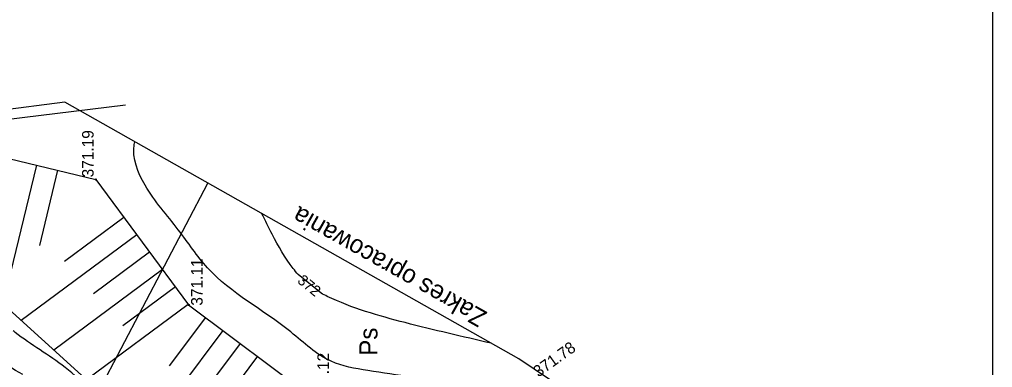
# Model space of a CAD drawing. Extents: x 4635329 to 4651863, y 5356628 to 5367582.
# Drawn here: x 4651263.7 to 4651331.2, y 5356725 to 5356749.2 of the extents above; entities that cross this region are included whole.
import ezdxf

# ---------------------------------------------------------------- set-up
doc = ezdxf.new("R2010")
doc.units = 0
for name, color, linetype in [('Level 1', 7, 'Continuous'), ('Level 12', 7, 'Continuous'), ('Level 13', 7, 'Continuous'), ('Level 39', 7, 'Continuous'), ('Level 4', 7, 'Continuous'), ('Level 44', 7, 'Continuous'), ('Level 45', 7, 'Continuous'), ('Level 46', 7, 'Continuous'), ('Level 47', 7, 'Continuous'), ('Level 48', 7, 'Continuous'), ('Level 6', 7, 'Continuous')]:
    doc.layers.add(name, color=color, linetype=linetype)

msp = doc.modelspace()

# ---------------------------------------------------------------- linework, layer by layer
at = {"layer": 'Level 1'}
for p, q in [((4651266.84, 5356743.443), (4651230.35, 5356738.707)), ((4651298.345, 5356725.644), (4651266.84, 5356743.443)), ((4651328.793, 5356705.271), (4651298.345, 5356725.644))]:
    msp.add_line(p, q, dxfattribs=at)
at = {"layer": 'Level 13'}
msp.add_lwpolyline([(4651092.18, 5356627.729), (4651092.18, 5356813.355), (4651331.195, 5356813.355), (4651331.195, 5356627.729)], close=True, dxfattribs=at)
at = {"layer": 'Level 39'}
msp.add_lwpolyline([(4651250.035, 5356740.377), (4651256.705, 5356741.507), (4651271.061, 5356743.246)], dxfattribs=at)
at = {"layer": 'Level 4'}
msp.add_line((4651265.88, 5356717.076), (4651276.761, 5356737.838), dxfattribs=at)
at = {"layer": 'Level 44'}
for centre in [(4651268.995, 5356738.077), (4651275.435, 5356729.397)]:
    msp.add_circle(centre, 0.04, dxfattribs=at)
at = {"layer": 'Level 46'}
msp.add_line((4651284.619, 5356730.193), (4651283.033, 5356731.486), dxfattribs=at)
for points in [[(4651267.161, 5356715.987), (4651264.708, 5356717.442), (4651260.614, 5356719.868), (4651257.43, 5356722.141), (4651254.792, 5356725.021), (4651252.517, 5356728.872), (4651246.741, 5356739.5), (4651245.898, 5356740.725)], [(4651298.334, 5356723.071), (4651293.949, 5356723.874), (4651287.864, 5356724.843), (4651285.317, 5356725.479), (4651282.527, 5356727.511), (4651276.752, 5356731.958), (4651274.72, 5356734.595), (4651272.415, 5356737.688), (4651271.657, 5356740.507), (4651271.694, 5356740.701)], [(4651283.033, 5356731.486), (4651282.686, 5356731.921), (4651281.229, 5356734.288), (4651280.522, 5356735.713)], [(4651263.931, 5356724.554), (4651261.972, 5356725.806), (4651257.58, 5356731.092)], [(4651296.426, 5356726.728), (4651290.455, 5356728.159), (4651285.053, 5356729.979), (4651284.619, 5356730.193)], [(4651268.687, 5356723.452), (4651266.865, 5356725.056), (4651263.408, 5356727.482), (4651263.267, 5356727.595)], [(4651276.186, 5356713.946), (4651274.753, 5356715.814), (4651267.627, 5356718.36), (4651265.018, 5356720.21), (4651263.442, 5356721.998), (4651259.59, 5356724.848), (4651257.237, 5356726.91)]]:
    msp.add_spline(points, degree=3, dxfattribs=at)
at = {"layer": 'Level 48'}
for p, q in [((4651264.883, 5356739.071), (4651262.556, 5356729.448)), ((4651266.341, 5356738.719), (4651265.081, 5356733.511)), ((4651270.943, 5356735.451), (4651266.816, 5356732.39)), ((4651271.837, 5356734.247), (4651263.823, 5356728.301)), ((4651272.731, 5356733.042), (4651268.844, 5356730.158)), ((4651273.624, 5356731.837), (4651266.091, 5356726.248)), ((4651274.518, 5356730.633), (4651270.872, 5356727.927)), ((4651275.412, 5356729.428), (4651268.359, 5356724.195)), ((4651276.605, 5356728.522), (4651274.097, 5356725.17)), ((4651277.806, 5356727.623), (4651272.839, 5356720.985)), ((4651279.007, 5356726.724), (4651276.548, 5356723.438)), ((4651280.208, 5356725.826), (4651275.338, 5356719.317))]:
    msp.add_line(p, q, dxfattribs=at)
for points in [[(4651283.295, 5356714.007), (4651269.285, 5356723.357), (4651257.365, 5356734.147), (4651256.135, 5356741.187)], [(4651256.135, 5356741.187), (4651268.995, 5356738.077), (4651275.435, 5356729.397), (4651284.135, 5356722.887), (4651292.525, 5356718.537)]]:
    msp.add_lwpolyline(points, dxfattribs=at)

# ---------------------------------------------------------------- texts
at = {"layer": 'Level 12'}
msp.add_text('Ps', height=1.25, rotation=90, dxfattribs=at).set_placement((4651288.531, 5356725.864))
at = {"layer": 'Level 45'}
for s, rotation, p in [('371.19', 90, (4651268.845, 5356738.227)), ('371.11', 90, (4651276.406, 5356729.335)), ('371.78', 35.65672, (4651299.703, 5356724.345)), ('371.12', 90, (4651285.167, 5356722.795))]:
    msp.add_text(s, height=0.8, rotation=rotation, dxfattribs=at).set_placement(p)
at = {"layer": 'Level 47'}
msp.add_text('372', height=0.75, rotation=320.68961, dxfattribs=at).set_placement((4651282.922, 5356730.978))
at = {"layer": 'Level 6'}
msp.add_text('Zakres opracowania', height=1.25, rotation=150.53538, dxfattribs=at).set_placement((4651296.208, 5356728.861))

doc.saveas('drawing.dxf')
